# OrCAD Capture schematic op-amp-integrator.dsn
size A
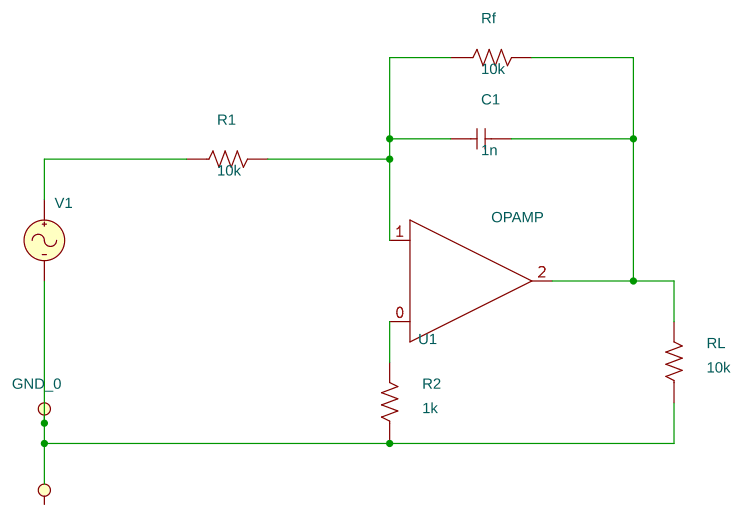
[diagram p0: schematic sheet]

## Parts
C1  1n  [cap196]
R1  10k  [AXRC05]
R2  1k  [AXRC05]
Rf  10k  [AXRC05]
RL  10k  [AXRC05]
U1  OPAMP
V1  VAC

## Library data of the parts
C1 = C
R1 R2 Rf RL = R
U1 = OPAMP
V1 = VAC

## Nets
0: R2.1 RL.1 V1.2(-)
N15135: C1.1 R1.2 Rf.1 U1.1(-)
N15143: C1.2 Rf.2 RL.2 U1.2(OUT)
N15199: R1.1 V1.1(+)
N15269: R2.2 U1.0(+)
